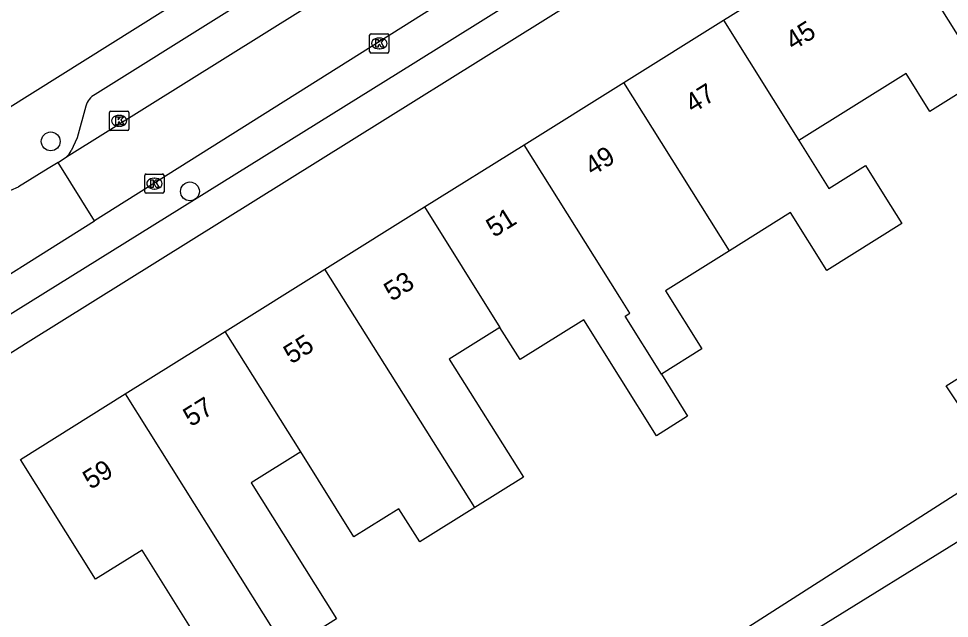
# Model space of a CAD drawing. Extents: x 159353 to 160616, y 385893 to 387321.
# Drawn here: x 159682.26 to 159730.58, y 386027.3 to 386058.45 of the extents above; entities that cross this region are included whole.
import ezdxf

# ---------------------------------------------------------------- set-up
doc = ezdxf.new("R2010")
doc.units = 0
for name, color, linetype in [('IMGEO_Boom', 7, 'Continuous'), ('IMGEO_Kolk', 7, 'Continuous'), ('IMGEO_Pand', 7, 'Continuous'), ('IMGEO_Pand_nummerreeks', 7, 'Continuous'), ('IMGEO_Rijbaan_lokaal_open', 7, 'Continuous'), ('IMGEO_Voetpad_open', 7, 'Continuous')]:
    doc.layers.add(name, color=color, linetype=linetype)

msp = doc.modelspace()

# ---------------------------------------------------------------- linework, layer by layer
at = {"layer": 'IMGEO_Boom'}
for centre in [(159683.927, 386052.079), (159691.156, 386049.481)]:
    msp.add_circle(centre, 0.489, dxfattribs=at)
at = {"layer": 'IMGEO_Kolk'}
for p, q in [((159700.484, 386056.741), (159700.484, 386057.593)), ((159700.559, 386057.667), (159701.411, 386057.667)), ((159700.972, 386057.447), (159700.997, 386057.447)), ((159701.485, 386057.593), (159701.485, 386056.741)), ((159701.411, 386056.667), (159700.559, 386056.667)), ((159700.995, 386056.887), (159700.97, 386056.887)), ((159687.057, 386053.645), (159687.909, 386053.645)), ((159686.982, 386052.719), (159686.982, 386053.571)), ((159687.47, 386053.425), (159687.495, 386053.425)), ((159687.983, 386053.571), (159687.983, 386052.719)), ((159687.909, 386052.645), (159687.057, 386052.645)), ((159687.493, 386052.865), (159687.468, 386052.865)), ((159688.811, 386049.457), (159688.811, 386050.309)), ((159688.886, 386050.383), (159689.738, 386050.383)), ((159689.812, 386050.309), (159689.812, 386049.457)), ((159689.299, 386050.163), (159689.324, 386050.163)), ((159689.738, 386049.383), (159688.886, 386049.383)), ((159689.322, 386049.603), (159689.297, 386049.603))]:
    msp.add_line(p, q, dxfattribs=at)
for points in [[(159700.484, 386056.741), (159700.484, 386057.593)], [(159700.559, 386057.667), (159701.411, 386057.667)], [(159701.485, 386057.593), (159701.485, 386056.741)], [(159700.805, 386057.367), (159700.928, 386057.367), (159700.928, 386057.216), (159701.058, 386057.367), (159701.222, 386057.367), (159701.076, 386057.216), (159701.229, 386056.967), (159701.077, 386056.967), (159700.992, 386057.131), (159700.928, 386057.064), (159700.928, 386056.967), (159700.805, 386056.967), (159700.805, 386057.367)], [(159701.411, 386056.667), (159700.559, 386056.667)], [(159687.057, 386053.645), (159687.909, 386053.645)], [(159686.982, 386052.719), (159686.982, 386053.571)], [(159687.303, 386053.345), (159687.426, 386053.345), (159687.426, 386053.194), (159687.556, 386053.345), (159687.72, 386053.345), (159687.574, 386053.194), (159687.727, 386052.945), (159687.575, 386052.945), (159687.49, 386053.109), (159687.426, 386053.042), (159687.426, 386052.945), (159687.303, 386052.945), (159687.303, 386053.345)], [(159687.983, 386053.571), (159687.983, 386052.719)], [(159687.909, 386052.645), (159687.057, 386052.645)], [(159688.811, 386049.457), (159688.811, 386050.309)], [(159688.886, 386050.383), (159689.738, 386050.383)], [(159689.812, 386050.309), (159689.812, 386049.457)], [(159689.132, 386050.083), (159689.255, 386050.083), (159689.255, 386049.932), (159689.385, 386050.083), (159689.549, 386050.083), (159689.403, 386049.932), (159689.556, 386049.683), (159689.404, 386049.683), (159689.319, 386049.847), (159689.255, 386049.78), (159689.255, 386049.683), (159689.132, 386049.683), (159689.132, 386050.083)], [(159689.738, 386049.383), (159688.886, 386049.383)]]:
    msp.add_lwpolyline(points, dxfattribs=at)
for centre, start, end in [((159700.561, 386057.591), 91.552, 178.448), ((159700.561, 386057.591), 91.552, 178.448), ((159701.409, 386057.591), 1.552, 88.448), ((159701.409, 386057.591), 1.552, 88.448), ((159700.561, 386056.743), 181.552, 268.448), ((159700.561, 386056.743), 181.552, 268.448), ((159701.409, 386056.743), 271.552, 358.448), ((159701.409, 386056.743), 271.552, 358.448), ((159687.059, 386053.569), 91.552, 178.448), ((159687.059, 386053.569), 91.552, 178.448), ((159687.907, 386053.569), 1.552, 88.448), ((159687.907, 386053.569), 1.552, 88.448), ((159687.059, 386052.721), 181.552, 268.448), ((159687.059, 386052.721), 181.552, 268.448), ((159687.907, 386052.721), 271.552, 358.448), ((159687.907, 386052.721), 271.552, 358.448), ((159688.888, 386050.307), 91.552, 178.448), ((159688.888, 386050.307), 91.552, 178.448), ((159689.736, 386050.307), 1.552, 88.448), ((159689.736, 386050.307), 1.552, 88.448), ((159688.888, 386049.459), 181.552, 268.448), ((159688.888, 386049.459), 181.552, 268.448), ((159689.736, 386049.459), 271.552, 358.448), ((159689.736, 386049.459), 271.552, 358.448)]:
    msp.add_arc(centre, 0.0765, start, end, dxfattribs=at)
for centre, major_axis, ratio, start_param, end_param in [((159700.971, 386057.167), (-0.387, 0.002), 0.722429, 4.712389, 7.853982), ((159700.996, 386057.167), (-0.39, 0.002), 0.717154, 1.570796, 4.712389), ((159687.469, 386053.145), (-0.387, 0.002), 0.722429, 4.712389, 7.853982), ((159687.494, 386053.145), (-0.39, 0.002), 0.717154, 1.570796, 4.712389), ((159689.298, 386049.883), (-0.387, 0.002), 0.722429, 4.712389, 7.853982), ((159689.323, 386049.883), (-0.39, 0.002), 0.717154, 1.570796, 4.712389)]:
    msp.add_ellipse(centre, major_axis=major_axis, ratio=ratio, start_param=start_param, end_param=end_param, dxfattribs=at)
at = {"layer": 'IMGEO_Pand'}
for points in [[(159718.85, 386058.374), (159724.039, 386061.618), (159725.451, 386059.359), (159728.653, 386061.361), (159732.387, 386055.393), (159729.564, 386053.627), (159728.326, 386055.605), (159722.758, 386052.122)], [(159713.682, 386055.143), (159718.85, 386058.374)], [(159718.85, 386058.374), (159722.758, 386052.122)], [(159708.502, 386051.905), (159713.682, 386055.143)], [(159719.171, 386046.4), (159713.682, 386055.143)], [(159703.328, 386048.671), (159708.502, 386051.905)], [(159715.63, 386039.982), (159713.74, 386042.999), (159713.984, 386043.152), (159713.466, 386043.98), (159708.502, 386051.905)], [(159722.758, 386052.122), (159724.32, 386049.624), (159726.229, 386050.819), (159727.228, 386049.223), (159728.112, 386047.81), (159724.213, 386045.369), (159722.329, 386048.377), (159719.171, 386046.4)], [(159698.161, 386045.441), (159703.328, 386048.671)], [(159703.328, 386048.671), (159707.246, 386042.417)], [(159719.171, 386046.4), (159715.841, 386044.315), (159717.73, 386041.298), (159715.63, 386039.982)], [(159692.982, 386042.203), (159698.161, 386045.441)], [(159705.947, 386033.06), (159698.161, 386045.441)], [(159733.186, 386035.211), (159730.405, 386039.383), (159739.998, 386045.377)], [(159715.63, 386039.982), (159716.992, 386037.806), (159715.372, 386036.791), (159711.6, 386042.813), (159708.294, 386040.745), (159707.246, 386042.417)], [(159687.801, 386038.964), (159692.982, 386042.203)], [(159696.906, 386035.948), (159692.982, 386042.203)], [(159707.246, 386042.417), (159704.617, 386040.772), (159708.473, 386034.64), (159705.947, 386033.06)], [(159696.144, 386025.636), (159695.953, 386025.516), (159695.412, 386026.381), (159692.572, 386024.604), (159688.668, 386030.843), (159686.251, 386029.331), (159682.354, 386035.559), (159687.801, 386038.964)], [(159687.801, 386038.964), (159696.144, 386025.636)], [(159696.906, 386035.948), (159694.342, 386034.344), (159698.765, 386027.275), (159696.144, 386025.636)], [(159705.947, 386033.06), (159703.085, 386031.27), (159701.997, 386033), (159699.669, 386031.543), (159696.906, 386035.948)]]:
    msp.add_lwpolyline(points, dxfattribs=at)
at = {"layer": 'IMGEO_Rijbaan_lokaal_open'}
for points in [[(159684.747, 386051.268), (159715.668, 386070.601)], [(159717.543, 386067.695), (159686.194, 386047.956)], [(159684.308, 386050.988), (159684.747, 386051.268)], [(159684.308, 386050.988), (159683.792, 386050.662), (159682.262, 386049.724)], [(159686.194, 386047.956), (159684.308, 386050.988)], [(159678.382, 386043.037), (159686.194, 386047.956)], [(159711.277, 386019.075), (159743.822, 386039.222)]]:
    msp.add_lwpolyline(points, dxfattribs=at)
msp.add_arc((159679.482, 386055.181), 6.125, 231.8513, 296.9921, dxfattribs=at)
at = {"layer": 'IMGEO_Voetpad_open'}
for points in [[(159680.364, 386052.973), (159727.06, 386082.254)], [(159712.06, 386070.688), (159686.23, 386054.518)], [(159676.499, 386035.726), (159677.195, 386038.177), (159682.76, 386041.661), (159724.652, 386067.823)], [(159715.811, 386064.272), (159702.746, 386056.105), (159681.467, 386042.865)], [(159685.758, 386053.909), (159685.302, 386052.262), (159684.993, 386051.59)], [(159712.435, 386021.927), (159733.186, 386035.211)]]:
    msp.add_lwpolyline(points, dxfattribs=at)
for centre, radius, start, end in [((159686.728, 386053.644), 1.006, 119.703, 164.7427), ((159684.062, 386052.046), 1.036, 311.3464, 333.8958)]:
    msp.add_arc(centre, radius, start, end, dxfattribs=at)

# ---------------------------------------------------------------- texts
at = {"layer": 'IMGEO_Pand_nummerreeks'}
for s, p in [('45', (159722.472, 386056.77)), ('47', (159717.261, 386053.513)), ('49', (159712.05, 386050.256)), ('51', (159706.935, 386047.058)), ('53', (159701.629, 386043.741)), ('55', (159696.419, 386040.483)), ('57', (159691.208, 386037.226)), ('59', (159685.998, 386033.969))]:
    msp.add_text(s, height=1, rotation=32.0112, dxfattribs=at).set_placement(p)

doc.saveas('drawing.dxf')
